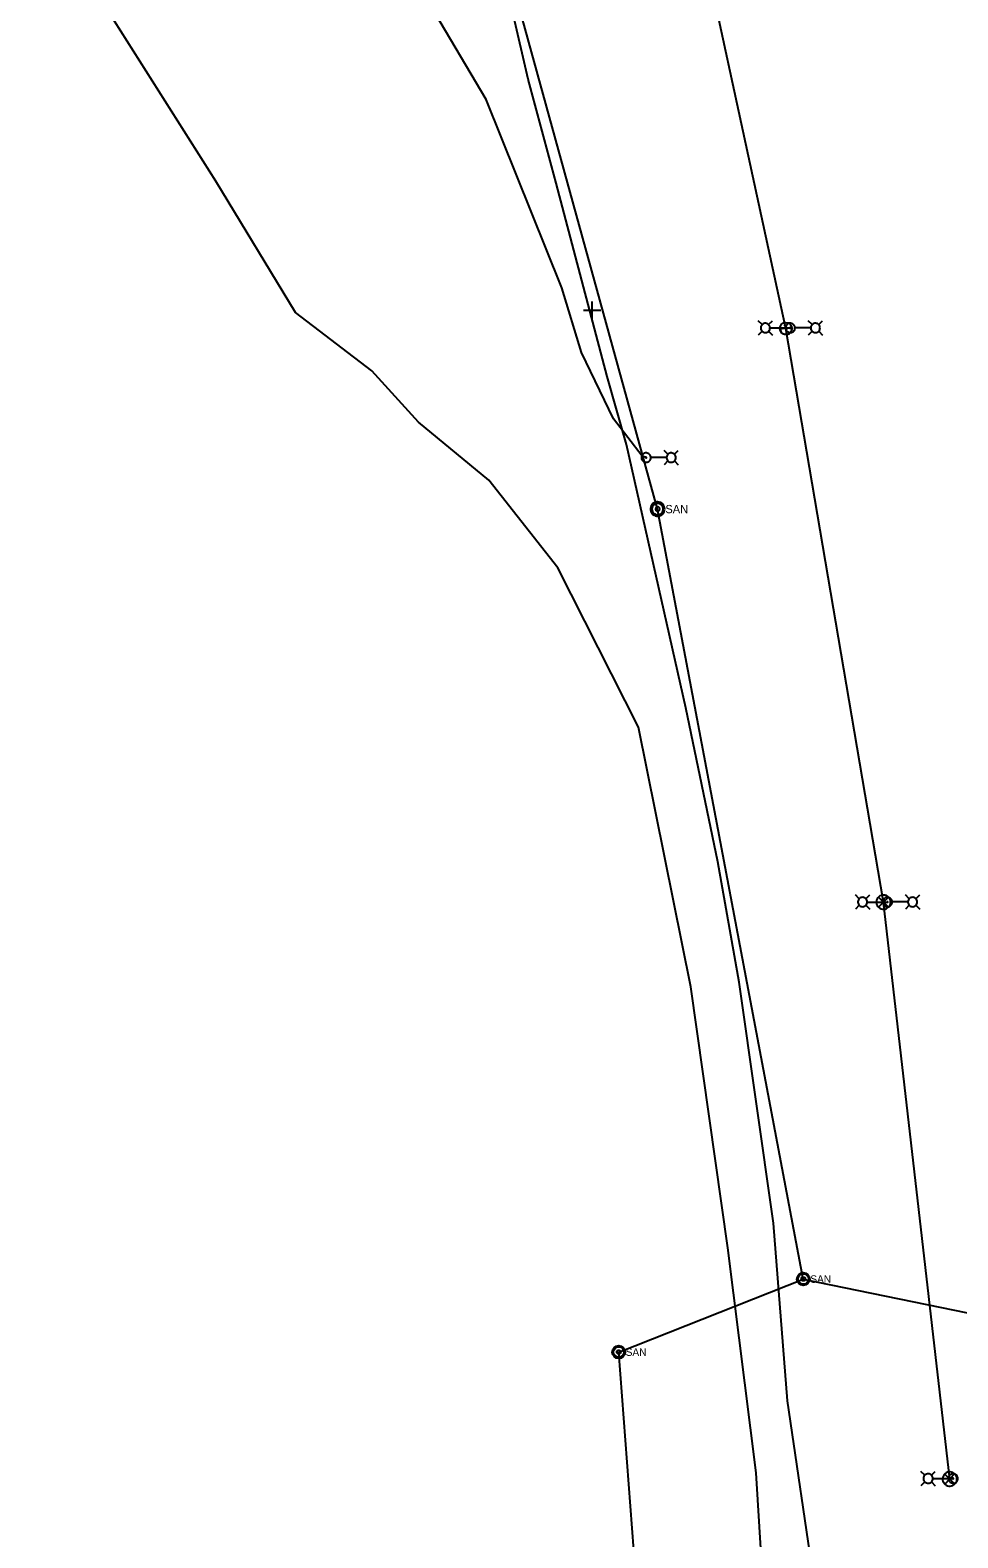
# Model space of a CAD drawing. Extents: x 596028 to 606371, y 330010 to 403088.
# Drawn here: x 603892 to 604322, y 348312 to 349011 of the extents above; entities that cross this region are included whole.
import ezdxf

# ---------------------------------------------------------------- set-up
doc = ezdxf.new("R2010")
doc.units = 0
for name, color, linetype in [('E_FTMS_Conduit', 7, 'Continuous'), ('E_LTG', 7, 'Continuous'), ('E_LTG_CID', 7, 'Continuous'), ('E_UTL_E_UG', 7, 'Continuous'), ('E_UTL_FO_UG_QWEST', 7, 'Continuous'), ('E_UTL_SAN_MH', 7, 'Continuous'), ('E_UTL_SAN_UG', 7, 'Continuous')]:
    doc.layers.add(name, color=color, linetype=linetype)

# ---------------------------------------------------------------- blocks, each defined once
blk = doc.blocks.new('_U272')
at = {"layer": 'E_LTG'}
blk.add_lwpolyline([(0.001, -0.171), (0.001, 0.172)], dxfattribs=at)
blk.add_circle((0.001, 0), 0.171, dxfattribs=at)
blk.add_arc((0.001, 0), 0.171, 90, 270, dxfattribs=at)
blk.add_text('L', height=0.108, dxfattribs=at).set_placement((0.066, -0.042))

msp = doc.modelspace()

# ---------------------------------------------------------------- linework, layer by layer
at = {"layer": 'E_FTMS_Conduit'}
for points in [[(604122.74, 348988.04), (604108.56, 349049.67), (604100.88, 349081.84), (604090.92, 349138.93), (604079.09, 349196.91), (604056.03, 349276.86), (604043.16, 349350.52), (604043.52, 349350.57), (604038.65, 349379.99), (604027.8, 349419.58), (604014.43, 349447.39), (603999.06, 349483.4), (603987.98, 349514.15), (603982.63, 349526.67)], [(604278.35, 347707.92), (604277.45, 347789.35), (604277.54, 347789.41), (604275.46, 347871.38), (604275.11, 347958.92), (604272.4, 348040.89), (604268.55, 348121.53), (604263.61, 348205.89), (604255.37, 348290.94), (604242.89, 348375.97), (604236.47, 348458.2), (604220.45, 348569.91), (604210.62, 348625.55), (604195.75, 348696.84), (604168.29, 348818.93), (604159.32, 348850.28), (604151.36, 348880.73), (604135.81, 348939.85), (604122.74, 348988.04)]]:
    msp.add_lwpolyline(points, dxfattribs=at)
at = {"layer": 'E_LTG'}
for points in [[(604231.12, 348874.38), (604229.35, 348876.15)], [(604234.82, 348872.85), (604234.78, 348873.27), (604234.67, 348873.66), (604234.48, 348874.03), (604234.22, 348874.36), (604233.91, 348874.63), (604233.55, 348874.83), (604233.16, 348874.97), (604232.75, 348875.03), (604232.34, 348875.01), (604231.94, 348874.91), (604231.56, 348874.74), (604231.22, 348874.5), (604230.94, 348874.2), (604230.71, 348873.85), (604230.56, 348873.47), (604230.48, 348873.06), (604230.48, 348872.65), (604230.56, 348872.24), (604230.71, 348871.86), (604230.94, 348871.51), (604231.22, 348871.21), (604231.56, 348870.97), (604231.94, 348870.8), (604232.34, 348870.7), (604232.75, 348870.68), (604233.16, 348870.74), (604233.55, 348870.88), (604233.91, 348871.08), (604234.22, 348871.35), (604234.48, 348871.68), (604234.67, 348872.05), (604234.78, 348872.44), (604234.82, 348872.85)], [(604234.17, 348874.38), (604235.95, 348876.15)], [(604234.86, 348872.85), (604242.04, 348872.85)], [(604246.39, 348872.85), (604246.35, 348873.27), (604246.23, 348873.66), (604246.04, 348874.03), (604245.79, 348874.36), (604245.48, 348874.63), (604245.12, 348874.83), (604244.73, 348874.97), (604244.32, 348875.03), (604243.9, 348875.01), (604243.5, 348874.91), (604243.13, 348874.74), (604242.79, 348874.5), (604242.5, 348874.2), (604242.28, 348873.85), (604242.13, 348873.47), (604242.05, 348873.06), (604242.05, 348872.65), (604242.13, 348872.24), (604242.28, 348871.86), (604242.5, 348871.51), (604242.79, 348871.21), (604243.13, 348870.97), (604243.5, 348870.8), (604243.9, 348870.7), (604244.32, 348870.68), (604244.73, 348870.74), (604245.12, 348870.88), (604245.48, 348871.08), (604245.79, 348871.35), (604246.04, 348871.68), (604246.23, 348872.05), (604246.35, 348872.44), (604246.39, 348872.85)], [(604244.38, 348872.85), (604244.38, 348872.89), (604244.37, 348872.92), (604244.35, 348872.94), (604244.33, 348872.97), (604244.31, 348872.99), (604244.28, 348873.01), (604244.25, 348873.02), (604244.22, 348873.02), (604244.19, 348873.02), (604244.16, 348873.01), (604244.13, 348873), (604244.1, 348872.98), (604244.08, 348872.96), (604244.07, 348872.93), (604244.05, 348872.9), (604244.05, 348872.87), (604244.05, 348872.84), (604244.05, 348872.81), (604244.07, 348872.78), (604244.08, 348872.75), (604244.1, 348872.73), (604244.13, 348872.71), (604244.16, 348872.7), (604244.19, 348872.69), (604244.22, 348872.69), (604244.25, 348872.69), (604244.28, 348872.7), (604244.31, 348872.72), (604244.33, 348872.74), (604244.35, 348872.76), (604244.37, 348872.79), (604244.38, 348872.82), (604244.38, 348872.85)], [(604253.6, 348872.85), (604246.43, 348872.85)], [(604254.29, 348874.38), (604252.52, 348876.15)], [(604257.99, 348872.85), (604257.95, 348873.27), (604257.84, 348873.66), (604257.65, 348874.03), (604257.39, 348874.36), (604257.08, 348874.63), (604256.72, 348874.83), (604256.33, 348874.97), (604255.92, 348875.03), (604255.51, 348875.01), (604255.1, 348874.91), (604254.73, 348874.74), (604254.39, 348874.5), (604254.11, 348874.2), (604253.88, 348873.85), (604253.73, 348873.47), (604253.65, 348873.06), (604253.65, 348872.65), (604253.73, 348872.24), (604253.88, 348871.86), (604254.11, 348871.51), (604254.39, 348871.21), (604254.73, 348870.97), (604255.1, 348870.8), (604255.51, 348870.7), (604255.92, 348870.68), (604256.33, 348870.74), (604256.72, 348870.88), (604257.08, 348871.08), (604257.39, 348871.35), (604257.65, 348871.68), (604257.84, 348872.05), (604257.95, 348872.44), (604257.99, 348872.85)], [(604257.34, 348874.38), (604259.12, 348876.15)], [(604231.12, 348871.33), (604229.35, 348869.55)], [(604234.17, 348871.33), (604235.95, 348869.55)], [(604254.29, 348871.33), (604252.52, 348869.55)], [(604257.34, 348871.33), (604259.12, 348869.55)], [(604187.52, 348814.31), (604185.74, 348816.09)], [(604190.57, 348814.31), (604192.34, 348816.09)], [(604179.61, 348812.79), (604179.57, 348813.2), (604179.46, 348813.6), (604179.27, 348813.96), (604179.01, 348814.29), (604178.7, 348814.56), (604178.34, 348814.77), (604177.95, 348814.9), (604177.54, 348814.96), (604177.13, 348814.94), (604176.72, 348814.84), (604176.35, 348814.67), (604176.01, 348814.43), (604175.73, 348814.13), (604175.5, 348813.78), (604175.35, 348813.4), (604175.27, 348812.99), (604175.27, 348812.58), (604175.35, 348812.17), (604175.5, 348811.79), (604175.73, 348811.44), (604176.01, 348811.14), (604176.35, 348810.9), (604176.72, 348810.73), (604177.13, 348810.63), (604177.54, 348810.61), (604177.95, 348810.67), (604178.34, 348810.81), (604178.7, 348811.02), (604179.01, 348811.29), (604179.27, 348811.61), (604179.46, 348811.98), (604179.57, 348812.38), (604179.61, 348812.79)], [(604177.6, 348812.79), (604177.6, 348812.82), (604177.59, 348812.85), (604177.58, 348812.88), (604177.56, 348812.9), (604177.53, 348812.92), (604177.51, 348812.94), (604177.48, 348812.95), (604177.44, 348812.95), (604177.41, 348812.95), (604177.38, 348812.94), (604177.35, 348812.93), (604177.33, 348812.91), (604177.31, 348812.89), (604177.29, 348812.86), (604177.28, 348812.83), (604177.27, 348812.8), (604177.27, 348812.77), (604177.28, 348812.74), (604177.29, 348812.71), (604177.31, 348812.68), (604177.33, 348812.66), (604177.35, 348812.64), (604177.38, 348812.63), (604177.41, 348812.62), (604177.44, 348812.62), (604177.48, 348812.63), (604177.51, 348812.64), (604177.53, 348812.65), (604177.56, 348812.67), (604177.58, 348812.7), (604177.59, 348812.73), (604177.6, 348812.76), (604177.6, 348812.79)], [(604186.83, 348812.79), (604179.65, 348812.79)], [(604187.52, 348811.27), (604185.74, 348809.49)], [(604191.22, 348812.79), (604191.18, 348813.2), (604191.06, 348813.6), (604190.87, 348813.96), (604190.61, 348814.29), (604190.3, 348814.56), (604189.94, 348814.77), (604189.55, 348814.9), (604189.14, 348814.96), (604188.73, 348814.94), (604188.33, 348814.84), (604187.95, 348814.67), (604187.62, 348814.43), (604187.33, 348814.13), (604187.11, 348813.78), (604186.95, 348813.4), (604186.87, 348812.99), (604186.87, 348812.58), (604186.95, 348812.17), (604187.11, 348811.79), (604187.33, 348811.44), (604187.62, 348811.14), (604187.95, 348810.9), (604188.33, 348810.73), (604188.73, 348810.63), (604189.14, 348810.61), (604189.55, 348810.67), (604189.94, 348810.81), (604190.3, 348811.02), (604190.61, 348811.29), (604190.87, 348811.61), (604191.06, 348811.98), (604191.18, 348812.38), (604191.22, 348812.79)], [(604190.57, 348811.27), (604192.34, 348809.49)], [(604276.13, 348608.49), (604274.36, 348610.26)], [(604279.83, 348606.97), (604279.79, 348607.38), (604279.68, 348607.77), (604279.49, 348608.14), (604279.23, 348608.47), (604278.92, 348608.74), (604278.56, 348608.94), (604278.17, 348609.08), (604277.76, 348609.14), (604277.35, 348609.12), (604276.95, 348609.02), (604276.57, 348608.85), (604276.23, 348608.61), (604275.95, 348608.31), (604275.72, 348607.96), (604275.57, 348607.58), (604275.49, 348607.17), (604275.49, 348606.76), (604275.57, 348606.35), (604275.72, 348605.97), (604275.95, 348605.62), (604276.23, 348605.32), (604276.57, 348605.08), (604276.95, 348604.91), (604277.35, 348604.81), (604277.76, 348604.79), (604278.17, 348604.85), (604278.56, 348604.99), (604278.92, 348605.19), (604279.23, 348605.46), (604279.49, 348605.79), (604279.68, 348606.16), (604279.79, 348606.55), (604279.83, 348606.97)], [(604279.18, 348608.49), (604280.96, 348610.26)], [(604279.87, 348606.96), (604287.05, 348606.96)], [(604290.66, 348606.91), (604290.6, 348607.53), (604290.42, 348608.13), (604290.14, 348608.69), (604289.75, 348609.18), (604289.27, 348609.6), (604288.73, 348609.91), (604288.14, 348610.11), (604287.52, 348610.2), (604286.89, 348610.17), (604286.28, 348610.03), (604285.71, 348609.76), (604285.2, 348609.4), (604284.77, 348608.95), (604284.43, 348608.42), (604284.19, 348607.84), (604284.07, 348607.22), (604284.07, 348606.59), (604284.19, 348605.98), (604284.43, 348605.39), (604284.77, 348604.87), (604285.2, 348604.41), (604285.71, 348604.05), (604286.28, 348603.79), (604286.89, 348603.64), (604287.52, 348603.61), (604288.14, 348603.7), (604288.73, 348603.91), (604289.27, 348604.22), (604289.75, 348604.63), (604290.14, 348605.12), (604290.42, 348605.68), (604290.6, 348606.28), (604290.66, 348606.91)], [(604289.62, 348609.24), (604285.01, 348604.58)], [(604285.01, 348609.19), (604289.66, 348604.54)], [(604291.4, 348606.96), (604291.36, 348607.38), (604291.24, 348607.77), (604291.05, 348608.14), (604290.8, 348608.47), (604290.49, 348608.74), (604290.13, 348608.94), (604289.74, 348609.08), (604289.33, 348609.14), (604288.91, 348609.12), (604288.51, 348609.02), (604288.14, 348608.85), (604287.8, 348608.61), (604287.51, 348608.31), (604287.29, 348607.96), (604287.14, 348607.58), (604287.06, 348607.17), (604287.06, 348606.76), (604287.14, 348606.35), (604287.29, 348605.97), (604287.51, 348605.62), (604287.8, 348605.32), (604288.14, 348605.08), (604288.51, 348604.91), (604288.91, 348604.81), (604289.33, 348604.79), (604289.74, 348604.85), (604290.13, 348604.99), (604290.49, 348605.19), (604290.8, 348605.46), (604291.05, 348605.79), (604291.24, 348606.16), (604291.36, 348606.55), (604291.4, 348606.96)], [(604289.39, 348606.96), (604289.39, 348607), (604289.38, 348607.03), (604289.36, 348607.05), (604289.34, 348607.08), (604289.32, 348607.1), (604289.29, 348607.12), (604289.26, 348607.13), (604289.23, 348607.13), (604289.2, 348607.13), (604289.17, 348607.12), (604289.14, 348607.11), (604289.11, 348607.09), (604289.09, 348607.07), (604289.08, 348607.04), (604289.06, 348607.01), (604289.06, 348606.98), (604289.06, 348606.95), (604289.06, 348606.92), (604289.08, 348606.89), (604289.09, 348606.86), (604289.11, 348606.84), (604289.14, 348606.82), (604289.17, 348606.81), (604289.2, 348606.8), (604289.23, 348606.8), (604289.26, 348606.8), (604289.29, 348606.81), (604289.32, 348606.83), (604289.34, 348606.85), (604289.36, 348606.87), (604289.38, 348606.9), (604289.39, 348606.93), (604289.39, 348606.96)], [(604298.61, 348606.97), (604291.44, 348606.97)], [(604299.3, 348608.49), (604297.53, 348610.26)], [(604303, 348606.96), (604302.96, 348607.38), (604302.85, 348607.77), (604302.66, 348608.14), (604302.4, 348608.47), (604302.09, 348608.74), (604301.73, 348608.94), (604301.34, 348609.08), (604300.93, 348609.14), (604300.52, 348609.12), (604300.11, 348609.02), (604299.74, 348608.85), (604299.4, 348608.61), (604299.12, 348608.31), (604298.89, 348607.96), (604298.74, 348607.58), (604298.66, 348607.17), (604298.66, 348606.76), (604298.74, 348606.35), (604298.89, 348605.97), (604299.12, 348605.62), (604299.4, 348605.32), (604299.74, 348605.08), (604300.11, 348604.91), (604300.52, 348604.81), (604300.93, 348604.79), (604301.34, 348604.85), (604301.73, 348604.99), (604302.09, 348605.19), (604302.4, 348605.46), (604302.66, 348605.79), (604302.85, 348606.16), (604302.96, 348606.55), (604303, 348606.96)], [(604302.35, 348608.49), (604304.13, 348610.26)], [(604276.13, 348605.44), (604274.36, 348603.66)], [(604279.18, 348605.44), (604280.96, 348603.66)], [(604299.3, 348605.44), (604297.53, 348603.67)], [(604302.35, 348605.44), (604304.13, 348603.67)], [(604306.51, 348341.46), (604304.73, 348343.23)], [(604310.21, 348339.93), (604310.17, 348340.35), (604310.06, 348340.74), (604309.87, 348341.11), (604309.61, 348341.44), (604309.3, 348341.71), (604308.94, 348341.91), (604308.55, 348342.05), (604308.14, 348342.11), (604307.73, 348342.09), (604307.32, 348341.99), (604306.95, 348341.82), (604306.61, 348341.58), (604306.33, 348341.28), (604306.1, 348340.93), (604305.95, 348340.55), (604305.87, 348340.14), (604305.87, 348339.73), (604305.95, 348339.32), (604306.1, 348338.94), (604306.33, 348338.59), (604306.61, 348338.29), (604306.95, 348338.05), (604307.32, 348337.88), (604307.73, 348337.78), (604308.14, 348337.76), (604308.55, 348337.82), (604308.94, 348337.96), (604309.3, 348338.16), (604309.61, 348338.43), (604309.87, 348338.76), (604310.06, 348339.13), (604310.17, 348339.52), (604310.21, 348339.93)], [(604309.56, 348341.46), (604311.34, 348343.23)], [(604321.35, 348339.7), (604321.29, 348340.33), (604321.11, 348340.93), (604320.82, 348341.49), (604320.44, 348341.98), (604319.96, 348342.39), (604319.42, 348342.7), (604318.83, 348342.91), (604318.21, 348343), (604317.58, 348342.97), (604316.97, 348342.82), (604316.4, 348342.56), (604315.89, 348342.2), (604315.45, 348341.74), (604315.12, 348341.21), (604314.88, 348340.63), (604314.76, 348340.02), (604314.76, 348339.39), (604314.88, 348338.77), (604315.12, 348338.19), (604315.45, 348337.66), (604315.89, 348337.21), (604316.4, 348336.84), (604316.97, 348336.58), (604317.58, 348336.44), (604318.21, 348336.41), (604318.83, 348336.49), (604319.42, 348336.7), (604319.96, 348337.01), (604320.44, 348337.42), (604320.82, 348337.92), (604321.11, 348338.48), (604321.29, 348339.08), (604321.35, 348339.7)], [(604320.31, 348342.04), (604315.7, 348337.38)], [(604315.7, 348341.99), (604320.35, 348337.34)], [(604321.78, 348339.93), (604321.74, 348340.35), (604321.62, 348340.74), (604321.43, 348341.11), (604321.18, 348341.44), (604320.86, 348341.71), (604320.51, 348341.91), (604320.11, 348342.05), (604319.7, 348342.11), (604319.29, 348342.09), (604318.89, 348341.99), (604318.51, 348341.82), (604318.18, 348341.58), (604317.89, 348341.28), (604317.67, 348340.93), (604317.51, 348340.55), (604317.44, 348340.14), (604317.44, 348339.73), (604317.51, 348339.32), (604317.67, 348338.94), (604317.89, 348338.59), (604318.18, 348338.29), (604318.51, 348338.05), (604318.89, 348337.88), (604319.29, 348337.78), (604319.7, 348337.76), (604320.11, 348337.82), (604320.51, 348337.96), (604320.86, 348338.16), (604321.18, 348338.43), (604321.43, 348338.76), (604321.62, 348339.13), (604321.74, 348339.52), (604321.78, 348339.93)], [(604306.51, 348338.41), (604304.73, 348336.63)], [(604309.56, 348338.41), (604311.34, 348336.63)], [(604310.25, 348339.93), (604317.43, 348339.93)], [(604319.77, 348339.93), (604319.76, 348339.97), (604319.76, 348340), (604319.74, 348340.02), (604319.72, 348340.05), (604319.7, 348340.07), (604319.67, 348340.09), (604319.64, 348340.1), (604319.61, 348340.1), (604319.58, 348340.1), (604319.55, 348340.09), (604319.52, 348340.08), (604319.49, 348340.06), (604319.47, 348340.04), (604319.45, 348340.01), (604319.44, 348339.98), (604319.44, 348339.95), (604319.44, 348339.92), (604319.44, 348339.89), (604319.45, 348339.86), (604319.47, 348339.83), (604319.49, 348339.81), (604319.52, 348339.79), (604319.55, 348339.78), (604319.58, 348339.77), (604319.61, 348339.77), (604319.64, 348339.77), (604319.67, 348339.78), (604319.7, 348339.8), (604319.72, 348339.82), (604319.74, 348339.84), (604319.76, 348339.87), (604319.76, 348339.9), (604319.77, 348339.93)]]:
    msp.add_lwpolyline(points, dxfattribs=at)
at = {"layer": 'E_LTG_CID'}
for points in [[(604318.05, 348339.7), (604287.36, 348606.91), (604242.16, 348872.6), (604188.57, 349120.13), (604125.01, 349362.84), (604050.82, 349602.08), (604014.23, 349708.06), (603966.43, 349837.54), (603869.82, 350091.09), (603838.85, 350172.22), (603784.41, 350315.72), (603699.29, 350539.43), (603613.87, 350764.2), (603510.34, 351036.54), (603442.84, 351213.06), (603357.76, 351436.96)], [(604177.44, 348812.79), (604175.61, 348813.39), (604162.29, 348830.79), (604147.42, 348861.43), (604138.4, 348891.47), (604103.33, 348978.71), (604077.58, 349022.17), (604075.59, 349036.8), (604061.65, 349050.32), (604030.89, 349079), (603967.67, 349152.06), (603951.25, 349172.14), (603937.49, 349182.11), (603904.88, 349203.77)], [(604242.16, 348872.6), (604244.21, 348872.85)], [(604318.05, 348339.7), (604319.6, 348339.93)]]:
    msp.add_lwpolyline(points, dxfattribs=at)
at = {"layer": 'E_UTL_E_UG'}
msp.add_lwpolyline([(604287.36, 348606.91), (604289.22, 348606.96)], dxfattribs=at)
at = {"layer": 'E_UTL_FO_UG_QWEST'}
msp.add_lwpolyline([(604249.05, 347549.01), (604252.11, 347738.65), (604253.43, 347830.05), (604250.54, 347934.17), (604247.61, 348023.5), (604245.83, 348087.57), (604236.13, 348217.46), (604228.32, 348342.51), (604215.3, 348446.76), (604198.19, 348567.61), (604173.84, 348687.96), (604136.54, 348761.74), (604104.56, 348802.29), (604071.95, 348829.22), (604050.35, 348852.97), (604014.99, 348880), (603978.11, 348940.82), (603910.71, 349047.53)], dxfattribs=at)
at = {"layer": 'E_UTL_SAN_MH'}
for points in [[(604186.04, 348788.97), (604185.98, 348789.59), (604185.8, 348790.19), (604185.52, 348790.75), (604185.13, 348791.24), (604184.66, 348791.65), (604184.11, 348791.97), (604183.52, 348792.17), (604182.9, 348792.26), (604182.27, 348792.23), (604181.66, 348792.09), (604181.09, 348791.82), (604180.58, 348791.46), (604180.15, 348791.01), (604179.81, 348790.48), (604179.57, 348789.9), (604179.46, 348789.28), (604179.46, 348788.65), (604179.57, 348788.04), (604179.81, 348787.45), (604180.15, 348786.93), (604180.58, 348786.47), (604181.09, 348786.11), (604181.66, 348785.85), (604182.27, 348785.7), (604182.9, 348785.67), (604183.52, 348785.76), (604184.11, 348785.97), (604184.66, 348786.28), (604185.13, 348786.69), (604185.52, 348787.18), (604185.8, 348787.74), (604185.98, 348788.34), (604186.04, 348788.97)], [(604185.38, 348788.97), (604185.33, 348789.47), (604185.19, 348789.95), (604184.96, 348790.39), (604184.65, 348790.79), (604184.27, 348791.12), (604183.84, 348791.37), (604183.36, 348791.53), (604182.87, 348791.6), (604182.37, 348791.58), (604181.88, 348791.46), (604181.42, 348791.25), (604181.01, 348790.96), (604180.67, 348790.6), (604180.39, 348790.18), (604180.21, 348789.71), (604180.11, 348789.22), (604180.11, 348788.72), (604180.21, 348788.22), (604180.39, 348787.76), (604180.67, 348787.33), (604181.01, 348786.97), (604181.42, 348786.68), (604181.88, 348786.47), (604182.37, 348786.35), (604182.87, 348786.33), (604183.36, 348786.4), (604183.84, 348786.57), (604184.27, 348786.82), (604184.65, 348787.15), (604184.96, 348787.54), (604185.19, 348787.99), (604185.33, 348788.47), (604185.38, 348788.97)], [(604183.73, 348788.97), (604183.71, 348789.15), (604183.66, 348789.33), (604183.57, 348789.5), (604183.46, 348789.65), (604183.32, 348789.77), (604183.15, 348789.87), (604182.97, 348789.93), (604182.79, 348789.96), (604182.6, 348789.95), (604182.42, 348789.9), (604182.25, 348789.82), (604182.09, 348789.72), (604181.96, 348789.58), (604181.86, 348789.42), (604181.79, 348789.25), (604181.76, 348789.06), (604181.76, 348788.87), (604181.79, 348788.69), (604181.86, 348788.51), (604181.96, 348788.35), (604182.09, 348788.22), (604182.25, 348788.11), (604182.42, 348788.03), (604182.6, 348787.99), (604182.79, 348787.98), (604182.97, 348788), (604183.15, 348788.07), (604183.32, 348788.16), (604183.46, 348788.28), (604183.57, 348788.43), (604183.66, 348788.6), (604183.71, 348788.78), (604183.73, 348788.97)]]:
    msp.add_lwpolyline(points, dxfattribs=at)
for centre, radius in [((604250.23, 348432.35), 3), ((604250.23, 348432.35), 2.4), ((604250.23, 348432.35), 0.9), ((604164.73, 348398.52), 3), ((604164.73, 348398.52), 2.4), ((604164.73, 348398.52), 0.9)]:
    msp.add_circle(centre, radius, dxfattribs=at)
at = {"layer": 'E_UTL_SAN_UG'}
for p, q in [((604182.74, 348788.97), (604086.4, 349138.2)), ((604250.22, 348432.34), (604182.74, 348788.97)), ((604164.73, 348398.52), (604250.22, 348432.34)), ((604188.69, 348084.12), (604164.73, 348398.52))]:
    msp.add_line(p, q, dxfattribs=at)
for points in [[(604148.47, 348881.04), (604156.47, 348881.04)], [(604152.47, 348877.04), (604152.47, 348885.04)], [(604250.22, 348432.34), (604472.45, 348386.77)]]:
    msp.add_lwpolyline(points, dxfattribs=at)

# ---------------------------------------------------------------- block references
at = {"layer": 'E_LTG_CID', "xscale": 16.404166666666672, "yscale": 16.404166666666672, "rotation": 97.82095686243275}
msp.add_blockref('_U272', (604242.17, 348872.59), dxfattribs=at)

# ---------------------------------------------------------------- texts
at = {"layer": 'E_UTL_SAN_MH'}
for height, p in [(3.849, (604186.31, 348787.02)), (3.499, (604253.47, 348430.58)), (3.499, (604167.97, 348396.75))]:
    msp.add_text('SAN', height=height, dxfattribs=at).set_placement(p)

doc.saveas('drawing.dxf')
